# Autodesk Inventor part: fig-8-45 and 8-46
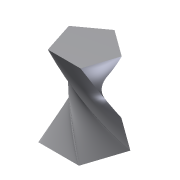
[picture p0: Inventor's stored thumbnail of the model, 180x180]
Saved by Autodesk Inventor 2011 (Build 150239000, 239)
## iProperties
Shininess: 64.0
Length Units: 11269
Angle Units: 11279
Time Units: 11290
Mass Units: 11283
Length Display Precision: 3
Angle Display Precision: 2
Compacted: True
Part Number: fig-8-45 and 8-46
Document SubType Name: Modeling
Created: 2002-12
Designer: deepak
Density: 1 g/cm^3
Density: 0.0
Volumn: 0.0
Area: 0.0
PropertySet Name: Model Information
Control State: 0
Master: False
Checked Out: False
Author: deepak
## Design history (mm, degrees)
sketch "Sketch1"
  geometry: L1 (0, 21.819)-(20.751, 6.743); L2 (20.751, 6.743)-(12.825, -17.652); L3 (12.825, -17.652)-(-12.825, -17.652); L4 (-12.825, -17.652)-(-20.751, 6.743); L5 (-20.751, 6.743)-(0, 21.819); 1 further point
  constraints: 10 end point, 9 other
workplane "Work Plane1"
sketch "Sketch2"
  geometry: L1 (0, 8.24)-(7.836, 2.546); L2 (7.836, 2.546)-(4.843, -6.666); L3 (4.843, -6.666)-(-4.843, -6.666); L4 (-4.843, -6.666)-(-7.836, 2.546); L5 (-7.836, 2.546)-(0, 8.24); 1 further point
  constraints: 10 end point, 9 other
workplane "Work Plane2"
sketch "Sketch3"
  geometry: L1 (0, 17.494)-(16.637, 5.406); L2 (16.637, 5.406)-(10.283, -14.153); L3 (10.283, -14.153)-(-10.283, -14.153); L4 (-10.283, -14.153)-(-16.637, 5.406); L5 (-16.637, 5.406)-(0, 17.494); 1 further point
  constraints: 10 end point, 9 other
loft "Loft4" sketch "Sketch3" dims "d20" = 0, "d21" = 90 deg, "d22" = 0, "d23" = 90 deg, "d24" = 0, "d25" = 90 deg
body "Solid1"
other parameters: "d0" = 25, "d1" = 25
